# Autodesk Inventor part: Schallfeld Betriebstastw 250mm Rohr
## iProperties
Shininess: 20.0
Length Units: 11269
Angle Units: 11279
Time Units: 11290
Mass Units: 11283
Length Display Precision: 3
Angle Display Precision: 2
Part Number: Schallfeld Betriebstastw 250mm Rohr
Material: Lexan (klar)
Document SubType Name: Modellieren
Description: Schallfeld 0,25 m
Checked By: Alves
Created: 2005-08
Designer: Klein
Manufacturer: Standard
Standards Organization: Custom
Density: 0.0
Volumn: 0.0
Area: 0.0
PropertySet Name: Model Information
Control State: 0
Master: False
Checked Out: False
Last Check In By: Kramp
Last Check In Date: 2005-08-11
BESTELLNUMMER: 0,25 m
ME: ST
Title: Schallfelder
Author: Klein
Comments: keine Bemerkung
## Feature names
1. Innenglocke [Revolution]
